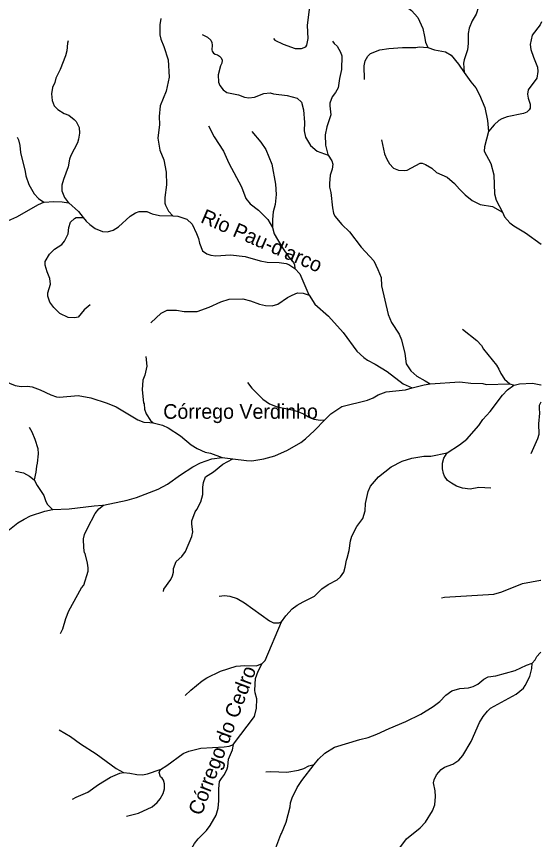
# Model space of a CAD drawing. Extents: x 500 to 555.2, y 9115.7 to 9171.
# Drawn here: x 549.39 to 555.12, y 9126.76 to 9135.74 of the extents above; entities that cross this region are included whole.
import ezdxf
from ezdxf.enums import TextEntityAlignment as Align

# ---------------------------------------------------------------- set-up
doc = ezdxf.new("R2010")
doc.units = 0
doc.header["$LTSCALE"] = 0.064
doc.layers.add('61', color=7, linetype='Continuous')
doc.layers.add('7', color=7, linetype='Continuous', lineweight=25)

msp = doc.modelspace()

# ---------------------------------------------------------------- linework, layer by layer
at = {"layer": '7'}
msp.add_line((551.6359, 9130.93), (551.7507, 9130.9153), dxfattribs=at)
for points in [[(554.4621, 9136.2076), (554.4621, 9136.063), (554.4521, 9135.9286), (554.4375, 9135.8478), (554.4113, 9135.7664), (554.3677, 9135.6948), (554.3343, 9135.6143), (554.3228, 9135.5552), (554.3227, 9135.4476), (554.3162, 9135.376), (554.2802, 9135.2671), (554.2736, 9135.231), (554.2804, 9135.1319)], [(552.1951, 9135.5009), (552.2125, 9135.4837), (552.3031, 9135.4389), (552.432, 9135.3938), (552.5008, 9135.3921), (552.5484, 9135.412), (552.5614, 9135.4277), (552.5742, 9135.5), (552.5663, 9135.642), (552.5905, 9135.821), (552.5853, 9135.9473), (552.6006, 9135.9839), (552.6205, 9136.0123), (552.6646, 9136.049)], [(553.3015, 9135.8833), (553.3053, 9135.8833), (553.4665, 9135.9035), (553.5256, 9135.9002), (553.5703, 9135.8892), (553.645, 9135.8518), (553.7023, 9135.8057), (553.7715, 9135.7312), (553.826, 9135.611), (553.8469, 9135.5237), (553.8552, 9135.4614), (553.8834, 9135.402)], [(550.9647, 9135.7188), (550.9537, 9135.6504), (550.9561, 9135.5415), (550.9666, 9135.4941), (550.9993, 9135.4153), (551.0455, 9135.2698), (551.0587, 9135.081), (551.0239, 9134.9254), (550.9601, 9134.7679), (550.9488, 9134.6517), (550.952, 9134.5618), (550.934, 9134.4131), (550.9539, 9134.2825), (550.9969, 9134.179), (551.0242, 9134.0429), (551.0274, 9133.9057), (551.0091, 9133.7656), (551.0108, 9133.7036), (551.0165, 9133.6814), (551.0505, 9133.6171), (551.0956, 9133.5661)], [(555.1245, 9135.6844), (555.1095, 9135.6491), (555.0223, 9135.5373), (555.0019, 9135.4372), (555.0069, 9135.382), (555.035, 9135.2961), (555.0798, 9135.1871), (555.0856, 9135.1401), (555.0722, 9135.0672), (554.9775, 9134.9422), (554.9724, 9134.8931), (554.9789, 9134.8506), (555, 9134.7837), (555.0011, 9134.7423), (554.9886, 9134.7225), (554.9636, 9134.699), (554.927, 9134.6834), (554.7492, 9134.6471), (554.6908, 9134.6261), (554.6575, 9134.6061), (554.6077, 9134.5612), (554.5454, 9134.4874)], [(551.4187, 9135.5457), (551.4757, 9135.5161), (551.511, 9135.484), (551.5228, 9135.4589), (551.5277, 9135.4296), (551.5228, 9135.3763), (551.5278, 9135.3639), (551.5429, 9135.3431), (551.5606, 9135.329), (551.5833, 9135.3244), (551.6085, 9135.3077), (551.6237, 9135.2898), (551.6352, 9135.2639), (551.6326, 9135.2333), (551.6181, 9135.203), (551.5922, 9135.1054), (551.5966, 9135.0233), (551.6115, 9134.9884), (551.6468, 9134.9415), (551.6859, 9134.9128), (551.8125, 9134.8883), (551.8807, 9134.8625), (551.928, 9134.8538), (551.9893, 9134.8614), (552.0894, 9134.9014), (552.1587, 9134.9094), (552.1982, 9134.8968), (552.3452, 9134.8798), (552.4547, 9134.8517), (552.5018, 9134.806), (552.525, 9134.7225), (552.5348, 9134.5848), (552.5316, 9134.4936), (552.5474, 9134.4263), (552.5989, 9134.3323), (552.6721, 9134.2719), (552.7919, 9134.23)], [(549.9534, 9135.4751), (549.9447, 9135.4518), (549.9383, 9135.3661), (549.9251, 9135.3132), (549.868, 9135.1627), (549.8198, 9135.0669), (549.8082, 9135.0232), (549.7844, 9134.9659), (549.7727, 9134.8991), (549.7782, 9134.8254), (549.8018, 9134.7655), (549.842, 9134.7272), (549.9115, 9134.6843), (549.9607, 9134.6636), (550.0198, 9134.6194), (550.0404, 9134.5941), (550.0727, 9134.5305), (550.0776, 9134.4687), (550.0679, 9134.4017), (550.0555, 9134.3631), (549.9815, 9134.2234), (549.9679, 9134.1845), (549.9541, 9134.1006), (549.9016, 9133.9629), (549.8844, 9133.8997), (549.8842, 9133.8408), (549.9148, 9133.7674), (549.9592, 9133.7096)], [(552.8394, 9135.474), (552.8588, 9135.4462), (552.8927, 9135.4176), (552.9296, 9135.3535), (552.9433, 9135.3119), (552.94, 9135.1634), (552.9171, 9135.0637), (552.9022, 9134.962), (552.8755, 9134.9112), (552.8385, 9134.8637), (552.8121, 9134.7974), (552.8105, 9134.7684), (552.8219, 9134.6673), (552.7788, 9134.5374), (552.7613, 9134.451), (552.7661, 9134.3394), (552.7889, 9134.2347), (552.7919, 9134.23)], [(553.1914, 9135.0553), (553.1878, 9135.2048), (553.1981, 9135.2566), (553.2263, 9135.3071), (553.2556, 9135.3377), (553.3585, 9135.3769), (553.4556, 9135.3933), (553.6069, 9135.4049), (553.7513, 9135.4032), (553.788, 9135.4098), (553.8834, 9135.402)], [(553.8834, 9135.402), (553.8835, 9135.4017), (553.9536, 9135.3767), (554.0761, 9135.3574), (554.1358, 9135.3195), (554.2157, 9135.2218), (554.2804, 9135.1319)], [(554.2804, 9135.1319), (554.3538, 9135.03), (554.4077, 9134.9646), (554.4474, 9134.8866), (554.5062, 9134.7494), (554.5358, 9134.605), (554.5454, 9134.4874)], [(551.4874, 9134.548), (551.5481, 9134.4299), (551.6516, 9134.271), (551.7076, 9134.1428), (551.8456, 9133.8848), (551.8943, 9133.7569), (551.9428, 9133.6989), (552.0329, 9133.6268), (552.133, 9133.5284), (552.1857, 9133.4409)], [(549.3961, 9134.4246), (549.4105, 9134.395), (549.4265, 9134.3354), (549.4349, 9134.2562), (549.4837, 9134.0506), (549.4903, 9134.0018), (549.5235, 9133.9101), (549.5817, 9133.8078), (549.6282, 9133.7566), (549.6889, 9133.7156)], [(551.9598, 9134.4872), (552.0589, 9134.372), (552.1133, 9134.2895), (552.177, 9134.1294), (552.22, 9133.9116), (552.2265, 9133.7989), (552.2149, 9133.6908), (552.1922, 9133.6104), (552.1839, 9133.5284), (552.1857, 9133.4409)], [(554.5454, 9134.4874), (554.5002, 9134.3196), (554.4984, 9134.2705), (554.5715, 9134.1367), (554.6018, 9134.0146), (554.6115, 9133.808), (554.629, 9133.7391), (554.6961, 9133.6051)], [(553.3776, 9134.3966), (553.4105, 9134.2449), (553.434, 9134.184), (553.4645, 9134.1336), (553.5071, 9134.0866), (553.5623, 9134.0663), (553.6244, 9134.0595), (553.6552, 9134.0666), (553.7972, 9134.1404), (553.8195, 9134.1403), (553.8574, 9134.1284), (553.9248, 9134.0869), (553.9755, 9134.0383), (554.0931, 9133.9877), (554.1731, 9133.9208), (554.2272, 9133.8586), (554.2901, 9133.7974), (554.3671, 9133.7352), (554.4536, 9133.6915), (554.5889, 9133.6692), (554.6961, 9133.6051)], [(552.7919, 9134.23), (552.8328, 9134.1659), (552.8464, 9134.1297), (552.8383, 9134.0763), (552.8167, 9134.0092), (552.8071, 9133.9193), (552.8089, 9133.8795), (552.8234, 9133.8211), (552.8403, 9133.6537), (552.8526, 9133.5955), (552.865, 9133.564), (552.9421, 9133.4722), (553.0269, 9133.3923), (553.1544, 9133.2239), (553.2913, 9133.0767), (553.338, 9132.982), (553.3712, 9132.8926), (553.3765, 9132.8028), (553.4488, 9132.4912), (553.4839, 9132.4046), (553.569, 9132.2767), (553.5945, 9132.2156), (553.63, 9132.0648), (553.6459, 9131.9533), (553.6984, 9131.8761), (553.7612, 9131.8177), (553.8541, 9131.7656), (553.9078, 9131.7341)], [(549.2942, 9133.5123), (549.3921, 9133.5564), (549.6302, 9133.6918), (549.6889, 9133.7156)], [(549.6889, 9133.7156), (549.6932, 9133.7173), (549.7971, 9133.7236), (549.8882, 9133.7202), (549.9592, 9133.7096)], [(549.9592, 9133.7096), (549.9612, 9133.707), (550.0657, 9133.6158), (550.1178, 9133.5502)], [(550.1178, 9133.5502), (550.1516, 9133.5077), (550.1899, 9133.4706), (550.2482, 9133.4293), (550.3297, 9133.3975), (550.3817, 9133.3907), (550.4437, 9133.4114), (550.5038, 9133.4462), (550.6327, 9133.5632), (550.689, 9133.6002), (550.729, 9133.6153), (550.8142, 9133.6136), (550.8723, 9133.5873), (550.951, 9133.571), (551.0956, 9133.5661)], [(554.6961, 9133.6051), (554.7201, 9133.5572), (554.7792, 9133.4903), (554.8204, 9133.4559), (554.9489, 9133.3795), (555.1216, 9133.2569)], [(550.194, 9132.597), (550.1298, 9132.5422), (550.0617, 9132.4628), (550.0264, 9132.4528), (549.9537, 9132.4592), (549.8639, 9132.5011), (549.7959, 9132.5667), (549.7533, 9132.6265), (549.7333, 9132.6892), (549.7333, 9132.7274), (549.7624, 9132.8212), (549.7531, 9132.8848), (549.7235, 9132.9543), (549.7034, 9133.0268), (549.7024, 9133.0695), (549.7501, 9133.1467), (549.8034, 9133.2015), (549.8842, 9133.2543), (549.9154, 9133.291), (549.9542, 9133.3697), (549.9597, 9133.4398), (549.9798, 9133.496), (550.0215, 9133.5378), (550.0417, 9133.5496), (550.1178, 9133.5502)], [(551.0956, 9133.5661), (551.1518, 9133.5642), (551.2489, 9133.5316), (551.3078, 9133.4741), (551.3571, 9133.3742), (551.377, 9133.3211), (551.3871, 9133.268), (551.4208, 9133.1833), (551.4694, 9133.151), (551.5119, 9133.1363), (551.5651, 9133.1286), (551.7252, 9133.1397), (551.888, 9133.1233), (552.0493, 9133.0758), (552.1281, 9133.061), (552.2593, 9133.0593), (552.3366, 9133.0464), (552.365, 9133.0343), (552.431, 9132.992)], [(552.1857, 9133.4409), (552.2048, 9133.3719), (552.2859, 9133.2293), (552.3655, 9133.1166), (552.4163, 9133.0581), (552.4264, 9133.0304), (552.431, 9132.992)], [(552.431, 9132.992), (552.4832, 9132.9325), (552.5817, 9132.7055), (552.5848, 9132.7006)], [(550.8564, 9132.399), (550.9706, 9132.5052), (551.0357, 9132.536), (551.1373, 9132.5393), (551.2226, 9132.523), (551.3615, 9132.5241), (551.4948, 9132.5717), (551.6202, 9132.6294), (551.7135, 9132.6572), (551.8621, 9132.6623), (551.9439, 9132.6395), (552.0448, 9132.6029), (552.1097, 9132.59), (552.181, 9132.5837), (552.2454, 9132.6045), (552.3506, 9132.6751), (552.4014, 9132.7029), (552.4586, 9132.7251), (552.5202, 9132.7247), (552.5848, 9132.7006)], [(552.5848, 9132.7006), (552.6479, 9132.6023), (552.7973, 9132.4721), (552.9576, 9132.2955), (553.1086, 9132.0886), (553.1822, 9132.0198), (553.2216, 9131.9919), (553.3058, 9131.9472), (553.437, 9131.8668), (553.6128, 9131.7349), (553.7126, 9131.6893)], [(554.2621, 9132.3287), (554.4162, 9132.208), (554.4702, 9132.152), (554.491, 9132.1122), (554.6328, 9131.9374), (554.6592, 9131.8943), (554.6793, 9131.8448), (554.7198, 9131.7849), (554.7796, 9131.7335)], [(549.0939, 9132.0794), (549.1509, 9132.0308), (549.1772, 9131.9931), (549.242, 9131.8211), (549.2641, 9131.7834), (549.2874, 9131.7569), (549.3143, 9131.7394), (549.3764, 9131.7142), (549.4413, 9131.7062), (549.5109, 9131.7077), (549.5593, 9131.7027), (549.6479, 9131.67), (549.7637, 9131.6144), (549.8252, 9131.5929), (549.8594, 9131.5898), (550.0646, 9131.606), (550.2018, 9131.5816), (550.381, 9131.5234), (550.4779, 9131.4813), (550.7151, 9131.3404), (550.7804, 9131.3172), (550.8453, 9131.3103), (550.8807, 9131.3074), (550.8816, 9131.3072)], [(550.8027, 9132.0328), (550.8124, 9131.927), (550.7913, 9131.8297), (550.7679, 9131.7753), (550.7618, 9131.6693), (550.7766, 9131.5262), (550.783, 9131.5166), (550.7881, 9131.4578), (550.8044, 9131.406), (550.8527, 9131.3343), (550.8816, 9131.3072)], [(551.9125, 9131.749), (551.9608, 9131.6848), (552.0802, 9131.5679), (552.1531, 9131.5163), (552.2358, 9131.4832), (552.3679, 9131.4566), (552.4504, 9131.4369), (552.5257, 9131.4047), (552.5773, 9131.3726), (552.6385, 9131.3467), (552.7112, 9131.3381), (552.7569, 9131.3396)], [(553.7126, 9131.6893), (553.844, 9131.7241), (553.9078, 9131.7341)], [(553.9078, 9131.7341), (554.2303, 9131.7568), (554.3524, 9131.7422), (554.482, 9131.7358), (554.5178, 9131.7258), (554.7796, 9131.7335), (554.8249, 9131.7205)], [(554.095, 9130.9801), (554.2273, 9131.0671), (554.3091, 9131.1315), (554.4391, 9131.28), (554.4824, 9131.3441), (554.5643, 9131.431), (554.6972, 9131.6098), (554.7526, 9131.6683), (554.8224, 9131.7199), (554.8249, 9131.7205)], [(554.8249, 9131.7205), (554.882, 9131.7343), (555.0255, 9131.7404), (555.1151, 9131.7242), (555.1197, 9131.7234)], [(552.7569, 9131.3396), (552.8235, 9131.4073), (552.943, 9131.487), (553.2232, 9131.5566), (553.2842, 9131.5821), (553.3416, 9131.6148), (553.4258, 9131.6449), (553.6389, 9131.6698), (553.7126, 9131.6893)], [(555.0127, 9130.9725), (555.0851, 9131.1357), (555.0984, 9131.1849), (555.0937, 9131.2967), (555.1052, 9131.4152), (555.1003, 9131.4662), (555.1037, 9131.5019), (555.1102, 9131.517), (555.1195, 9131.5384)], [(550.8816, 9131.3072), (550.9831, 9131.2812), (551.0474, 9131.2524), (551.1795, 9131.1668), (551.2975, 9131.0693), (551.3618, 9131.0279), (551.4485, 9130.9895), (551.5094, 9130.9774), (551.6359, 9130.93)], [(551.7507, 9130.9153), (551.9018, 9130.8959), (551.9615, 9130.8942), (552.0894, 9130.9156), (552.2107, 9130.9469), (552.3498, 9131.0083), (552.4944, 9131.0926), (552.5459, 9131.133), (552.6444, 9131.2252), (552.7569, 9131.3396)], [(549.5292, 9131.2612), (549.5579, 9131.2117), (549.5907, 9131.1298), (549.6235, 9131.0265), (549.6249, 9130.9696), (549.615, 9130.8674), (549.6068, 9130.8339), (549.6018, 9130.769), (549.581, 9130.6874)], [(550.338, 9130.4113), (550.5985, 9130.4649), (550.6997, 9130.4934), (550.9359, 9130.5852), (551.0389, 9130.64), (551.1805, 9130.742), (551.3158, 9130.8293), (551.3985, 9130.8726), (551.522, 9130.9147), (551.6343, 9130.9302), (551.6359, 9130.93)], [(550.9934, 9129.4664), (551.0002, 9129.4932), (551.0759, 9129.6006), (551.0944, 9129.6404), (551.1028, 9129.6792), (551.1031, 9129.7201), (551.1333, 9129.796), (551.1947, 9129.8509), (551.237, 9129.9062), (551.3044, 9130.0686), (551.3145, 9130.1199), (551.3033, 9130.2016), (551.3048, 9130.2407), (551.3421, 9130.3358), (551.3604, 9130.3611), (551.4028, 9130.4474), (551.4244, 9130.5267), (551.4245, 9130.6054), (551.4327, 9130.6586), (551.4556, 9130.7181), (551.5419, 9130.7736), (551.6431, 9130.8584), (551.7507, 9130.9153)], [(553.0221, 9129.9172), (553.0369, 9130.0222), (553.0511, 9130.0727), (553.1053, 9130.1784), (553.1707, 9130.2637), (553.1972, 9130.3481), (553.2009, 9130.4283), (553.2306, 9130.5601), (553.2563, 9130.6166), (553.3425, 9130.7208), (553.4818, 9130.8265), (553.6032, 9130.8895), (553.706, 9130.9236), (553.8372, 9130.9433), (553.9136, 9130.9463), (554.0938, 9130.9793), (554.095, 9130.9801)], [(554.5709, 9130.5946), (554.4404, 9130.6021), (554.3431, 9130.5858), (554.261, 9130.5955), (554.196, 9130.6179), (554.1391, 9130.6492), (554.0965, 9130.6809), (554.0653, 9130.7269), (554.0538, 9130.7548), (554.044, 9130.8055), (554.0408, 9130.8692), (554.0564, 9130.9222), (554.095, 9130.9801)], [(549.3801, 9130.7809), (549.4648, 9130.761), (549.5298, 9130.7268), (549.581, 9130.6874)], [(549.581, 9130.6874), (549.5827, 9130.6861), (549.614, 9130.6247), (549.6869, 9130.5142), (549.71, 9130.4487), (549.7276, 9130.4166), (549.7821, 9130.3616)], [(549.7821, 9130.3616), (549.7847, 9130.3621), (549.9636, 9130.371), (550.2393, 9130.4038), (550.3301, 9130.4097), (550.338, 9130.4113)], [(549.8709, 9129.01), (549.8956, 9129.0603), (549.9289, 9129.1752), (549.9613, 9129.2571), (550.1007, 9129.5097), (550.1252, 9129.5383), (550.171, 9129.6896), (550.1727, 9129.7274), (550.166, 9129.776), (550.1383, 9129.8819), (550.1322, 9129.8901), (550.1237, 9129.9433), (550.1222, 9130.0418), (550.1332, 9130.0892), (550.1633, 9130.1581), (550.2493, 9130.3173), (550.2905, 9130.3688), (550.338, 9130.4113)], [(549.1834, 9130.0687), (549.3117, 9130.1461), (549.4058, 9130.2171), (549.4714, 9130.2579), (549.5431, 9130.2921), (549.7005, 9130.3446), (549.7821, 9130.3616)], [(552.2849, 9129.1383), (552.3308, 9129.2037), (552.4021, 9129.2784), (552.4546, 9129.3178), (552.5196, 9129.3559), (552.6459, 9129.4175), (552.7263, 9129.4975), (552.7946, 9129.5461), (552.8904, 9129.5958), (552.9291, 9129.6269), (552.9646, 9129.6804), (552.9809, 9129.7322), (552.994, 9129.8109), (552.9995, 9129.8334), (553.0221, 9129.9172)], [(554.0299, 9129.3973), (554.0626, 9129.4074), (554.6016, 9129.4376), (554.6896, 9129.4635), (554.9173, 9129.5558), (555.1118, 9129.5918), (555.1172, 9129.5928)], [(551.6029, 9129.4172), (551.6617, 9129.4244), (551.7208, 9129.4163), (551.8011, 9129.3911), (551.8802, 9129.3456), (552.1511, 9129.1473), (552.1977, 9129.1276), (552.2553, 9129.1276), (552.2849, 9129.1383)], [(552.0737, 9128.6812), (552.1071, 9128.717), (552.2849, 9129.1383)], [(555.0236, 9128.6867), (555.054, 9128.724), (555.0743, 9128.7589), (555.1085, 9128.7995), (555.1162, 9128.8078)], [(551.2324, 9128.3318), (551.2932, 9128.3927), (551.4157, 9128.4924), (551.4687, 9128.5254), (551.6169, 9128.5979), (551.7891, 9128.6538), (551.884, 9128.6616), (552.0105, 9128.6569), (552.0737, 9128.6812)], [(551.7582, 9127.7982), (551.7587, 9127.8009), (551.9901, 9128.1057), (552.0127, 9128.1948), (552.016, 9128.2987), (551.9971, 9128.3609), (551.9936, 9128.3904), (551.9994, 9128.5186), (552.03, 9128.5984), (552.0737, 9128.6812)], [(552.6422, 9127.58), (552.6887, 9127.6393), (552.7569, 9127.7042), (552.8635, 9127.7713), (553.1379, 9127.8546), (553.2297, 9127.8758), (553.3249, 9127.9102), (553.4584, 9127.9744), (553.6404, 9128.0497), (553.8065, 9128.1296), (553.9411, 9128.213), (554.0116, 9128.2685), (554.0785, 9128.3369), (554.1429, 9128.383), (554.2336, 9128.409), (554.3248, 9128.4187), (554.3759, 9128.4307), (554.4276, 9128.4553), (554.4922, 9128.5133), (554.5404, 9128.5388), (554.6266, 9128.5467), (554.8351, 9128.6078), (554.9598, 9128.6653), (555.0236, 9128.6867)], [(553.5748, 9126.6721), (553.6498, 9126.7683), (553.7984, 9126.8907), (553.8581, 9126.9521), (553.932, 9127.075), (553.9586, 9127.1412), (553.9668, 9127.2324), (553.9618, 9127.2927), (553.9457, 9127.3799), (553.9531, 9127.4126), (553.9788, 9127.4697), (554.0276, 9127.5249), (554.0631, 9127.5508), (554.1568, 9127.5847), (554.2219, 9127.6262), (554.2639, 9127.6802), (554.3558, 9127.8309), (554.4468, 9128.0387), (554.4882, 9128.1059), (554.5324, 9128.1642), (554.5669, 9128.1959), (554.8487, 9128.348), (554.926, 9128.4152), (554.9468, 9128.4434), (554.9961, 9128.5412), (555.0181, 9128.6266), (555.0236, 9128.6867)], [(549.8557, 9127.9588), (549.9793, 9127.8873), (550.0881, 9127.8051), (550.2603, 9127.6985), (550.4786, 9127.5361), (550.558, 9127.4919), (550.5582, 9127.4919)], [(550.9615, 9127.5272), (551.0298, 9127.5699), (551.2088, 9127.7023), (551.2733, 9127.7272), (551.4031, 9127.7595), (551.6589, 9127.7733), (551.7114, 9127.7809), (551.7582, 9127.7982)], [(551.2506, 9126.4218), (551.2671, 9126.5382), (551.2911, 9126.6412), (551.3344, 9126.719), (551.3735, 9126.7699), (551.4649, 9126.8602), (551.5051, 9126.9154), (551.5687, 9127.0263), (551.5917, 9127.1051), (551.5983, 9127.1838), (551.5984, 9127.315), (551.6082, 9127.3937), (551.6268, 9127.4291), (551.6614, 9127.4722), (551.6915, 9127.5316), (551.6984, 9127.5593), (551.7036, 9127.6375), (551.7474, 9127.7416), (551.7582, 9127.7982)], [(550.0001, 9127.2008), (550.0412, 9127.2244), (550.1694, 9127.2774), (550.2844, 9127.3609), (550.4178, 9127.4415), (550.5163, 9127.4867), (550.5582, 9127.4919)], [(550.5582, 9127.4919), (550.6267, 9127.4857), (550.7037, 9127.471), (550.764, 9127.4693), (550.8218, 9127.4773), (550.96, 9127.5263), (550.9615, 9127.5272)], [(550.5912, 9127.0156), (550.7202, 9127.0493), (550.8707, 9127.1194), (550.9253, 9127.1654), (550.9596, 9127.2047), (550.9927, 9127.2653), (551.006, 9127.3146), (551.0045, 9127.3708), (550.995, 9127.4103), (550.981, 9127.4302), (550.9608, 9127.4459), (550.9474, 9127.4935), (550.9615, 9127.5272)], [(551.8111, 9125.2947), (551.8642, 9125.3965), (551.9164, 9125.5666), (551.9378, 9125.6808), (551.933, 9125.7289), (551.9379, 9125.7839), (551.9346, 9125.8447), (551.9528, 9125.9378), (551.9785, 9125.9924), (551.997, 9126.0549), (552.0159, 9126.0836), (552.0837, 9126.2489), (552.1783, 9126.5568), (552.2759, 9126.8178), (552.285, 9126.8276), (552.3364, 9126.9509), (552.3774, 9127.1189), (552.3824, 9127.1608), (552.4004, 9127.2166), (552.4562, 9127.3314), (552.505, 9127.4047), (552.6422, 9127.58)], [(552.1121, 9127.5), (552.1674, 9127.5036), (552.3437, 9127.4971), (552.4713, 9127.5174), (552.5278, 9127.5378), (552.5809, 9127.566), (552.6422, 9127.58)]]:
    msp.add_lwpolyline(points, dxfattribs=at)

# ---------------------------------------------------------------- texts
at = {"layer": '61'}
for s, rotation, p in [("Rio Pau-d'arco", 336.801, (552.0374, 9133.2222)), ('Córrego do Cedro', 69.444, (551.7101, 9127.8164))]:
    msp.add_text(s, height=0.16, rotation=rotation, dxfattribs=at).set_placement(p, align=Align.CENTER)
msp.add_text('Córrego Verdinho', height=0.16, dxfattribs=at).set_placement((551.8366, 9131.3524), align=Align.CENTER)

doc.saveas('drawing.dxf')
